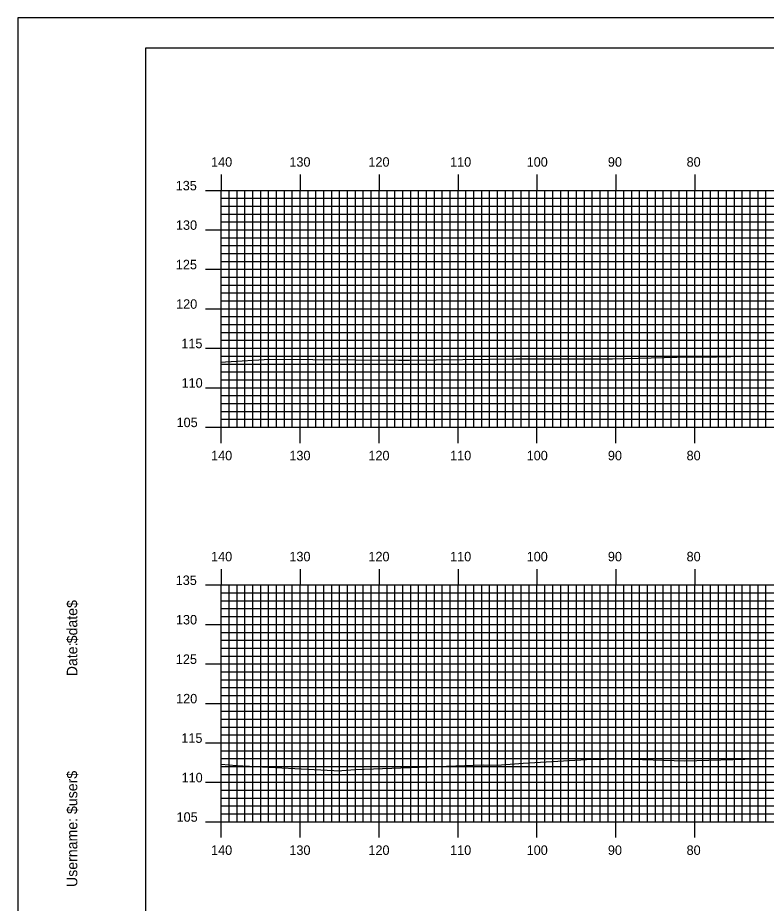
# Model space of a CAD drawing. Extents: x 1788550 to 1788893, y 442591 to 442811.
# Drawn here: x 1788549.9 to 1788644.7, y 442698.3 to 442810.5 of the extents above; entities that cross this region are included whole.
import ezdxf

# ---------------------------------------------------------------- set-up
doc = ezdxf.new("R2010")
doc.units = 0
for name, color, linetype in [('BORDER', 7, 'Continuous'), ('H_V ANNOTATION', 7, 'Continuous'), ('MAJOR', 7, 'Continuous'), ('MINOR', 7, 'Continuous'), ('PLOT BOUNDARY', 7, 'Continuous'), ('S_Roadway_Centerline', 7, 'Continuous')]:
    doc.layers.add(name, color=color, linetype=linetype)

msp = doc.modelspace()

# ---------------------------------------------------------------- linework, layer by layer
at = {"layer": 'BORDER'}
msp.add_lwpolyline([(1788566.04, 442596.67), (1788886.04, 442596.67), (1788886.04, 442806.67), (1788566.04, 442806.67)], close=True, dxfattribs=at)
at = {"layer": 'MAJOR'}
for p, q in [((1788575.64, 442790.67), (1788575.64, 442788.67)), ((1788585.64, 442790.67), (1788585.64, 442788.67)), ((1788595.64, 442790.67), (1788595.64, 442788.67)), ((1788605.64, 442790.67), (1788605.64, 442788.67)), ((1788615.64, 442790.67), (1788615.64, 442788.67)), ((1788625.64, 442790.67), (1788625.64, 442788.67)), ((1788635.64, 442790.67), (1788635.64, 442788.67)), ((1788573.64, 442788.67), (1788575.64, 442788.67)), ((1788575.64, 442788.67), (1788855.64, 442788.67)), ((1788575.64, 442758.67), (1788575.64, 442788.67)), ((1788575.64, 442758.67), (1788575.64, 442788.67)), ((1788575.64, 442788.67), (1788855.64, 442788.67)), ((1788585.64, 442758.67), (1788585.64, 442788.67)), ((1788595.64, 442758.67), (1788595.64, 442788.67)), ((1788605.64, 442758.67), (1788605.64, 442788.67)), ((1788615.64, 442758.67), (1788615.64, 442788.67)), ((1788625.64, 442758.67), (1788625.64, 442788.67)), ((1788635.64, 442758.67), (1788635.64, 442788.67)), ((1788573.64, 442783.67), (1788575.64, 442783.67)), ((1788575.64, 442783.67), (1788855.64, 442783.67)), ((1788573.64, 442778.67), (1788575.64, 442778.67)), ((1788575.64, 442778.67), (1788855.64, 442778.67)), ((1788573.64, 442773.67), (1788575.64, 442773.67)), ((1788575.64, 442773.67), (1788855.64, 442773.67)), ((1788573.64, 442768.67), (1788575.64, 442768.67)), ((1788575.64, 442768.67), (1788855.64, 442768.67)), ((1788573.64, 442763.67), (1788575.64, 442763.67)), ((1788575.64, 442763.67), (1788855.64, 442763.67)), ((1788573.64, 442758.67), (1788575.64, 442758.67)), ((1788575.64, 442758.67), (1788855.64, 442758.67)), ((1788575.64, 442758.67), (1788855.64, 442758.67)), ((1788575.64, 442756.66), (1788575.64, 442758.67)), ((1788585.64, 442756.66), (1788585.64, 442758.67)), ((1788595.64, 442756.66), (1788595.64, 442758.67)), ((1788605.64, 442756.66), (1788605.64, 442758.67)), ((1788615.64, 442756.66), (1788615.64, 442758.67)), ((1788625.64, 442756.66), (1788625.64, 442758.67)), ((1788635.64, 442756.66), (1788635.64, 442758.67)), ((1788575.64, 442740.67), (1788575.64, 442738.67)), ((1788585.64, 442740.67), (1788585.64, 442738.67)), ((1788595.64, 442740.67), (1788595.64, 442738.67)), ((1788605.64, 442740.67), (1788605.64, 442738.67)), ((1788615.64, 442740.67), (1788615.64, 442738.67)), ((1788625.64, 442740.67), (1788625.64, 442738.67)), ((1788635.64, 442740.67), (1788635.64, 442738.67)), ((1788573.64, 442738.67), (1788575.64, 442738.67)), ((1788575.64, 442738.67), (1788855.64, 442738.67)), ((1788575.64, 442708.67), (1788575.64, 442738.67)), ((1788575.64, 442708.67), (1788575.64, 442738.67)), ((1788575.64, 442738.67), (1788855.64, 442738.67)), ((1788585.64, 442708.67), (1788585.64, 442738.67)), ((1788595.64, 442708.67), (1788595.64, 442738.67)), ((1788605.64, 442708.67), (1788605.64, 442738.67)), ((1788615.64, 442708.67), (1788615.64, 442738.67)), ((1788625.64, 442708.67), (1788625.64, 442738.67)), ((1788635.64, 442708.67), (1788635.64, 442738.67)), ((1788573.64, 442733.67), (1788575.64, 442733.67)), ((1788575.64, 442733.67), (1788855.64, 442733.67)), ((1788573.64, 442728.67), (1788575.64, 442728.67)), ((1788575.64, 442728.67), (1788855.64, 442728.67)), ((1788573.64, 442723.67), (1788575.64, 442723.67)), ((1788575.64, 442723.67), (1788855.64, 442723.67)), ((1788573.64, 442718.67), (1788575.64, 442718.67)), ((1788575.64, 442718.67), (1788855.64, 442718.67)), ((1788573.64, 442713.67), (1788575.64, 442713.67)), ((1788575.64, 442713.67), (1788855.64, 442713.67)), ((1788573.64, 442708.67), (1788575.64, 442708.67)), ((1788575.64, 442708.67), (1788855.64, 442708.67)), ((1788575.64, 442708.67), (1788855.64, 442708.67)), ((1788575.64, 442706.66), (1788575.64, 442708.67)), ((1788585.64, 442706.66), (1788585.64, 442708.67)), ((1788595.64, 442706.66), (1788595.64, 442708.67)), ((1788605.64, 442706.66), (1788605.64, 442708.67)), ((1788615.64, 442706.66), (1788615.64, 442708.67)), ((1788625.64, 442706.66), (1788625.64, 442708.67)), ((1788635.64, 442706.66), (1788635.64, 442708.67))]:
    msp.add_line(p, q, dxfattribs=at)
at = {"layer": 'MINOR'}
for p, q in [((1788576.64, 442758.67), (1788576.64, 442788.67)), ((1788577.64, 442758.67), (1788577.64, 442788.67)), ((1788578.64, 442758.67), (1788578.64, 442788.67)), ((1788579.64, 442758.67), (1788579.64, 442788.67)), ((1788580.64, 442758.67), (1788580.64, 442788.67)), ((1788581.64, 442758.67), (1788581.64, 442788.67)), ((1788582.64, 442758.67), (1788582.64, 442788.67)), ((1788583.64, 442758.67), (1788583.64, 442788.67)), ((1788584.64, 442758.67), (1788584.64, 442788.67)), ((1788586.64, 442758.67), (1788586.64, 442788.67)), ((1788587.64, 442758.67), (1788587.64, 442788.67)), ((1788588.64, 442758.67), (1788588.64, 442788.67)), ((1788589.64, 442758.67), (1788589.64, 442788.67)), ((1788590.64, 442758.67), (1788590.64, 442788.67)), ((1788591.64, 442758.67), (1788591.64, 442788.67)), ((1788592.64, 442758.67), (1788592.64, 442788.67)), ((1788593.64, 442758.67), (1788593.64, 442788.67)), ((1788594.64, 442758.67), (1788594.64, 442788.67)), ((1788596.64, 442758.67), (1788596.64, 442788.67)), ((1788597.64, 442758.67), (1788597.64, 442788.67)), ((1788598.64, 442758.67), (1788598.64, 442788.67)), ((1788599.64, 442758.67), (1788599.64, 442788.67)), ((1788600.64, 442758.67), (1788600.64, 442788.67)), ((1788601.64, 442758.67), (1788601.64, 442788.67)), ((1788602.64, 442758.67), (1788602.64, 442788.67)), ((1788603.64, 442758.67), (1788603.64, 442788.67)), ((1788604.64, 442758.67), (1788604.64, 442788.67)), ((1788606.64, 442758.67), (1788606.64, 442788.67)), ((1788607.64, 442758.67), (1788607.64, 442788.67)), ((1788608.64, 442758.67), (1788608.64, 442788.67)), ((1788609.64, 442758.67), (1788609.64, 442788.67)), ((1788610.64, 442758.67), (1788610.64, 442788.67)), ((1788611.64, 442758.67), (1788611.64, 442788.67)), ((1788612.64, 442758.67), (1788612.64, 442788.67)), ((1788613.64, 442758.67), (1788613.64, 442788.67)), ((1788614.64, 442758.67), (1788614.64, 442788.67)), ((1788616.64, 442758.67), (1788616.64, 442788.67)), ((1788617.64, 442758.67), (1788617.64, 442788.67)), ((1788618.64, 442758.67), (1788618.64, 442788.67)), ((1788619.64, 442758.67), (1788619.64, 442788.67)), ((1788620.64, 442758.67), (1788620.64, 442788.67)), ((1788621.64, 442758.67), (1788621.64, 442788.67)), ((1788622.64, 442758.67), (1788622.64, 442788.67)), ((1788623.64, 442758.67), (1788623.64, 442788.67)), ((1788624.64, 442758.67), (1788624.64, 442788.67)), ((1788626.64, 442758.67), (1788626.64, 442788.67)), ((1788627.64, 442758.67), (1788627.64, 442788.67)), ((1788628.64, 442758.67), (1788628.64, 442788.67)), ((1788629.64, 442758.67), (1788629.64, 442788.67)), ((1788630.64, 442758.67), (1788630.64, 442788.67)), ((1788631.64, 442758.67), (1788631.64, 442788.67)), ((1788632.64, 442758.67), (1788632.64, 442788.67)), ((1788633.64, 442758.67), (1788633.64, 442788.67)), ((1788634.64, 442758.67), (1788634.64, 442788.67)), ((1788636.64, 442758.67), (1788636.64, 442788.67)), ((1788637.64, 442758.67), (1788637.64, 442788.67)), ((1788638.64, 442758.67), (1788638.64, 442788.67)), ((1788639.64, 442758.67), (1788639.64, 442788.67)), ((1788640.64, 442758.67), (1788640.64, 442788.67)), ((1788641.64, 442758.67), (1788641.64, 442788.67)), ((1788642.64, 442758.67), (1788642.64, 442788.67)), ((1788643.64, 442758.67), (1788643.64, 442788.67)), ((1788644.64, 442758.67), (1788644.64, 442788.67)), ((1788575.64, 442787.67), (1788855.64, 442787.67)), ((1788575.64, 442787.67), (1788577.65, 442787.67)), ((1788575.64, 442786.67), (1788855.64, 442786.67)), ((1788575.64, 442786.67), (1788577.65, 442786.67)), ((1788575.64, 442785.67), (1788855.64, 442785.67)), ((1788575.64, 442785.67), (1788577.65, 442785.67)), ((1788575.64, 442784.67), (1788855.64, 442784.67)), ((1788575.64, 442784.67), (1788577.65, 442784.67)), ((1788575.64, 442782.67), (1788855.64, 442782.67)), ((1788575.64, 442782.67), (1788577.65, 442782.67)), ((1788575.64, 442781.67), (1788855.64, 442781.67)), ((1788575.64, 442781.67), (1788577.65, 442781.67)), ((1788575.64, 442780.67), (1788855.64, 442780.67)), ((1788575.64, 442780.67), (1788577.65, 442780.67)), ((1788575.64, 442779.67), (1788855.64, 442779.67)), ((1788575.64, 442779.67), (1788577.65, 442779.67)), ((1788575.64, 442777.67), (1788855.64, 442777.67)), ((1788575.64, 442777.67), (1788577.65, 442777.67)), ((1788575.64, 442776.67), (1788855.64, 442776.67)), ((1788575.64, 442776.67), (1788577.65, 442776.67)), ((1788575.64, 442775.67), (1788855.64, 442775.67)), ((1788575.64, 442775.67), (1788577.65, 442775.67)), ((1788575.64, 442774.67), (1788855.64, 442774.67)), ((1788575.64, 442774.67), (1788577.65, 442774.67)), ((1788575.64, 442772.67), (1788855.64, 442772.67)), ((1788575.64, 442772.67), (1788577.65, 442772.67)), ((1788575.64, 442771.67), (1788855.64, 442771.67)), ((1788575.64, 442771.67), (1788577.65, 442771.67)), ((1788575.64, 442770.67), (1788855.64, 442770.67)), ((1788575.64, 442770.67), (1788577.65, 442770.67)), ((1788575.64, 442769.67), (1788855.64, 442769.67)), ((1788575.64, 442769.67), (1788577.65, 442769.67)), ((1788575.64, 442767.67), (1788855.64, 442767.67)), ((1788575.64, 442767.67), (1788577.65, 442767.67)), ((1788575.64, 442766.67), (1788855.64, 442766.67)), ((1788575.64, 442766.67), (1788577.65, 442766.67)), ((1788575.64, 442765.67), (1788855.64, 442765.67)), ((1788575.64, 442765.67), (1788577.65, 442765.67)), ((1788575.64, 442764.67), (1788855.64, 442764.67)), ((1788575.64, 442764.67), (1788577.65, 442764.67)), ((1788575.64, 442762.67), (1788855.64, 442762.67)), ((1788575.64, 442762.67), (1788577.65, 442762.67)), ((1788575.64, 442761.67), (1788855.64, 442761.67)), ((1788575.64, 442761.67), (1788577.65, 442761.67)), ((1788575.64, 442760.67), (1788855.64, 442760.67)), ((1788575.64, 442760.67), (1788577.65, 442760.67)), ((1788575.64, 442759.67), (1788855.64, 442759.67)), ((1788575.64, 442759.67), (1788577.65, 442759.67)), ((1788576.64, 442708.67), (1788576.64, 442738.67)), ((1788577.64, 442708.67), (1788577.64, 442738.67)), ((1788578.64, 442708.67), (1788578.64, 442738.67)), ((1788579.64, 442708.67), (1788579.64, 442738.67)), ((1788580.64, 442708.67), (1788580.64, 442738.67)), ((1788581.64, 442708.67), (1788581.64, 442738.67)), ((1788582.64, 442708.67), (1788582.64, 442738.67)), ((1788583.64, 442708.67), (1788583.64, 442738.67)), ((1788584.64, 442708.67), (1788584.64, 442738.67)), ((1788586.64, 442708.67), (1788586.64, 442738.67)), ((1788587.64, 442708.67), (1788587.64, 442738.67)), ((1788588.64, 442708.67), (1788588.64, 442738.67)), ((1788589.64, 442708.67), (1788589.64, 442738.67)), ((1788590.64, 442708.67), (1788590.64, 442738.67)), ((1788591.64, 442708.67), (1788591.64, 442738.67)), ((1788592.64, 442708.67), (1788592.64, 442738.67)), ((1788593.64, 442708.67), (1788593.64, 442738.67)), ((1788594.64, 442708.67), (1788594.64, 442738.67)), ((1788596.64, 442708.67), (1788596.64, 442738.67)), ((1788597.64, 442708.67), (1788597.64, 442738.67)), ((1788598.64, 442708.67), (1788598.64, 442738.67)), ((1788599.64, 442708.67), (1788599.64, 442738.67)), ((1788600.64, 442708.67), (1788600.64, 442738.67)), ((1788601.64, 442708.67), (1788601.64, 442738.67)), ((1788602.64, 442708.67), (1788602.64, 442738.67)), ((1788603.64, 442708.67), (1788603.64, 442738.67)), ((1788604.64, 442708.67), (1788604.64, 442738.67)), ((1788606.64, 442708.67), (1788606.64, 442738.67)), ((1788607.64, 442708.67), (1788607.64, 442738.67)), ((1788608.64, 442708.67), (1788608.64, 442738.67)), ((1788609.64, 442708.67), (1788609.64, 442738.67)), ((1788610.64, 442708.67), (1788610.64, 442738.67)), ((1788611.64, 442708.67), (1788611.64, 442738.67)), ((1788612.64, 442708.67), (1788612.64, 442738.67)), ((1788613.64, 442708.67), (1788613.64, 442738.67)), ((1788614.64, 442708.67), (1788614.64, 442738.67)), ((1788616.64, 442708.67), (1788616.64, 442738.67)), ((1788617.64, 442708.67), (1788617.64, 442738.67)), ((1788618.64, 442708.67), (1788618.64, 442738.67)), ((1788619.64, 442708.67), (1788619.64, 442738.67)), ((1788620.64, 442708.67), (1788620.64, 442738.67)), ((1788621.64, 442708.67), (1788621.64, 442738.67)), ((1788622.64, 442708.67), (1788622.64, 442738.67)), ((1788623.64, 442708.67), (1788623.64, 442738.67)), ((1788624.64, 442708.67), (1788624.64, 442738.67)), ((1788626.64, 442708.67), (1788626.64, 442738.67)), ((1788627.64, 442708.67), (1788627.64, 442738.67)), ((1788628.64, 442708.67), (1788628.64, 442738.67)), ((1788629.64, 442708.67), (1788629.64, 442738.67)), ((1788630.64, 442708.67), (1788630.64, 442738.67)), ((1788631.64, 442708.67), (1788631.64, 442738.67)), ((1788632.64, 442708.67), (1788632.64, 442738.67)), ((1788633.64, 442708.67), (1788633.64, 442738.67)), ((1788634.64, 442708.67), (1788634.64, 442738.67)), ((1788636.64, 442708.67), (1788636.64, 442738.67)), ((1788637.64, 442708.67), (1788637.64, 442738.67)), ((1788638.64, 442708.67), (1788638.64, 442738.67)), ((1788639.64, 442708.67), (1788639.64, 442738.67)), ((1788640.64, 442708.67), (1788640.64, 442738.67)), ((1788641.64, 442708.67), (1788641.64, 442738.67)), ((1788642.64, 442708.67), (1788642.64, 442738.67)), ((1788643.64, 442708.67), (1788643.64, 442738.67)), ((1788644.64, 442708.67), (1788644.64, 442738.67)), ((1788575.64, 442737.67), (1788855.64, 442737.67)), ((1788575.64, 442737.67), (1788577.65, 442737.67)), ((1788575.64, 442736.67), (1788855.64, 442736.67)), ((1788575.64, 442736.67), (1788577.65, 442736.67)), ((1788575.64, 442735.67), (1788855.64, 442735.67)), ((1788575.64, 442735.67), (1788577.65, 442735.67)), ((1788575.64, 442734.67), (1788855.64, 442734.67)), ((1788575.64, 442734.67), (1788577.65, 442734.67)), ((1788575.64, 442732.67), (1788855.64, 442732.67)), ((1788575.64, 442732.67), (1788577.65, 442732.67)), ((1788575.64, 442731.67), (1788855.64, 442731.67)), ((1788575.64, 442731.67), (1788577.65, 442731.67)), ((1788575.64, 442730.67), (1788855.64, 442730.67)), ((1788575.64, 442730.67), (1788577.65, 442730.67)), ((1788575.64, 442729.67), (1788855.64, 442729.67)), ((1788575.64, 442729.67), (1788577.65, 442729.67)), ((1788575.64, 442727.67), (1788855.64, 442727.67)), ((1788575.64, 442727.67), (1788577.65, 442727.67)), ((1788575.64, 442726.67), (1788855.64, 442726.67)), ((1788575.64, 442726.67), (1788577.65, 442726.67)), ((1788575.64, 442725.67), (1788855.64, 442725.67)), ((1788575.64, 442725.67), (1788577.65, 442725.67)), ((1788575.64, 442724.67), (1788855.64, 442724.67)), ((1788575.64, 442724.67), (1788577.65, 442724.67)), ((1788575.64, 442722.67), (1788855.64, 442722.67)), ((1788575.64, 442722.67), (1788577.65, 442722.67)), ((1788575.64, 442721.67), (1788855.64, 442721.67)), ((1788575.64, 442721.67), (1788577.65, 442721.67)), ((1788575.64, 442720.67), (1788855.64, 442720.67)), ((1788575.64, 442720.67), (1788577.65, 442720.67)), ((1788575.64, 442719.67), (1788855.64, 442719.67)), ((1788575.64, 442719.67), (1788577.65, 442719.67)), ((1788575.64, 442717.67), (1788855.64, 442717.67)), ((1788575.64, 442717.67), (1788577.65, 442717.67)), ((1788575.64, 442716.67), (1788855.64, 442716.67)), ((1788575.64, 442716.67), (1788577.65, 442716.67)), ((1788575.64, 442715.67), (1788855.64, 442715.67)), ((1788575.64, 442715.67), (1788577.65, 442715.67)), ((1788575.64, 442714.67), (1788855.64, 442714.67)), ((1788575.64, 442714.67), (1788577.65, 442714.67)), ((1788575.64, 442712.67), (1788855.64, 442712.67)), ((1788575.64, 442712.67), (1788577.65, 442712.67)), ((1788575.64, 442711.67), (1788855.64, 442711.67)), ((1788575.64, 442711.67), (1788577.65, 442711.67)), ((1788575.64, 442710.67), (1788855.64, 442710.67)), ((1788575.64, 442710.67), (1788577.65, 442710.67)), ((1788575.64, 442709.67), (1788855.64, 442709.67)), ((1788575.64, 442709.67), (1788577.65, 442709.67))]:
    msp.add_line(p, q, dxfattribs=at)
at = {"layer": 'PLOT BOUNDARY'}
msp.add_lwpolyline([(1788549.86, 442590.55), (1788889.86, 442590.55), (1788889.86, 442810.55), (1788549.86, 442810.55)], close=True, dxfattribs=at)
at = {"layer": 'S_Roadway_Centerline'}
for points in [[(1788575.64, 442766.9), (1788576.16, 442766.95), (1788581.79, 442767.29), (1788598.08, 442767.15), (1788599.49, 442767.16), (1788612.97, 442767.31), (1788619.61, 442767.31), (1788625.21, 442767.32), (1788634.99, 442767.56), (1788638.37, 442767.58), (1788642.05, 442767.65), (1788656.06, 442767.78)], [(1788575.64, 442715.97), (1788577.58, 442715.8), (1788590.7, 442715.14), (1788590.92, 442715.17), (1788592.62, 442715.29), (1788608.83, 442715.87), (1788610.58, 442715.85), (1788613.87, 442716.08), (1788621.9, 442716.57), (1788626.36, 442716.64), (1788634.38, 442716.37), (1788646.55, 442716.72)]]:
    msp.add_lwpolyline(points, dxfattribs=at)

# ---------------------------------------------------------------- texts
at = {"layer": 'BORDER'}
for s, p in [('$date$', (1788557.41, 442731.28)), ('Date:', (1788557.41, 442727.1)), ('$user$', (1788557.41, 442709.65)), ('Username:', (1788557.41, 442700.4))]:
    msp.add_text(s, height=1.339, rotation=90, dxfattribs=at).set_placement(p)
at = {"layer": 'H_V ANNOTATION'}
for s, p in [('140', (1788574.35, 442791.67)), ('130', (1788584.27, 442791.67)), ('120', (1788594.28, 442791.67)), ('110', (1788604.63, 442791.67)), ('100', (1788614.33, 442791.67)), ('90', (1788624.62, 442791.67)), ('80', (1788634.59, 442791.67)), ('135', (1788569.87, 442788.67)), ('130', (1788569.9, 442783.67)), ('125', (1788569.89, 442778.67)), ('120', (1788569.92, 442773.67)), ('115', (1788570.58, 442768.67)), ('110', (1788570.61, 442763.67)), ('105', (1788569.98, 442758.67)), ('140', (1788574.35, 442754.47)), ('130', (1788584.27, 442754.47)), ('120', (1788594.28, 442754.47)), ('110', (1788604.63, 442754.47)), ('100', (1788614.33, 442754.47)), ('90', (1788624.62, 442754.47)), ('80', (1788634.59, 442754.47)), ('140', (1788574.35, 442741.67)), ('130', (1788584.27, 442741.67)), ('120', (1788594.28, 442741.67)), ('110', (1788604.63, 442741.67)), ('100', (1788614.33, 442741.67)), ('90', (1788624.62, 442741.67)), ('80', (1788634.59, 442741.67)), ('135', (1788569.87, 442738.67)), ('130', (1788569.9, 442733.67)), ('125', (1788569.89, 442728.67)), ('120', (1788569.92, 442723.67)), ('115', (1788570.58, 442718.67)), ('110', (1788570.61, 442713.67)), ('105', (1788569.98, 442708.67)), ('140', (1788574.35, 442704.47)), ('130', (1788584.27, 442704.47)), ('120', (1788594.28, 442704.47)), ('110', (1788604.63, 442704.47)), ('100', (1788614.33, 442704.47)), ('90', (1788624.62, 442704.47)), ('80', (1788634.59, 442704.47))]:
    msp.add_text(s, height=1.2, dxfattribs=at).set_placement(p)
at = {"layer": 'MAJOR'}
for p in [(1788575.63, 442758.67), (1788575.63, 442708.67)]:
    msp.add_text('-', height=0.012, dxfattribs=at).set_placement(p)

doc.saveas('drawing.dxf')
